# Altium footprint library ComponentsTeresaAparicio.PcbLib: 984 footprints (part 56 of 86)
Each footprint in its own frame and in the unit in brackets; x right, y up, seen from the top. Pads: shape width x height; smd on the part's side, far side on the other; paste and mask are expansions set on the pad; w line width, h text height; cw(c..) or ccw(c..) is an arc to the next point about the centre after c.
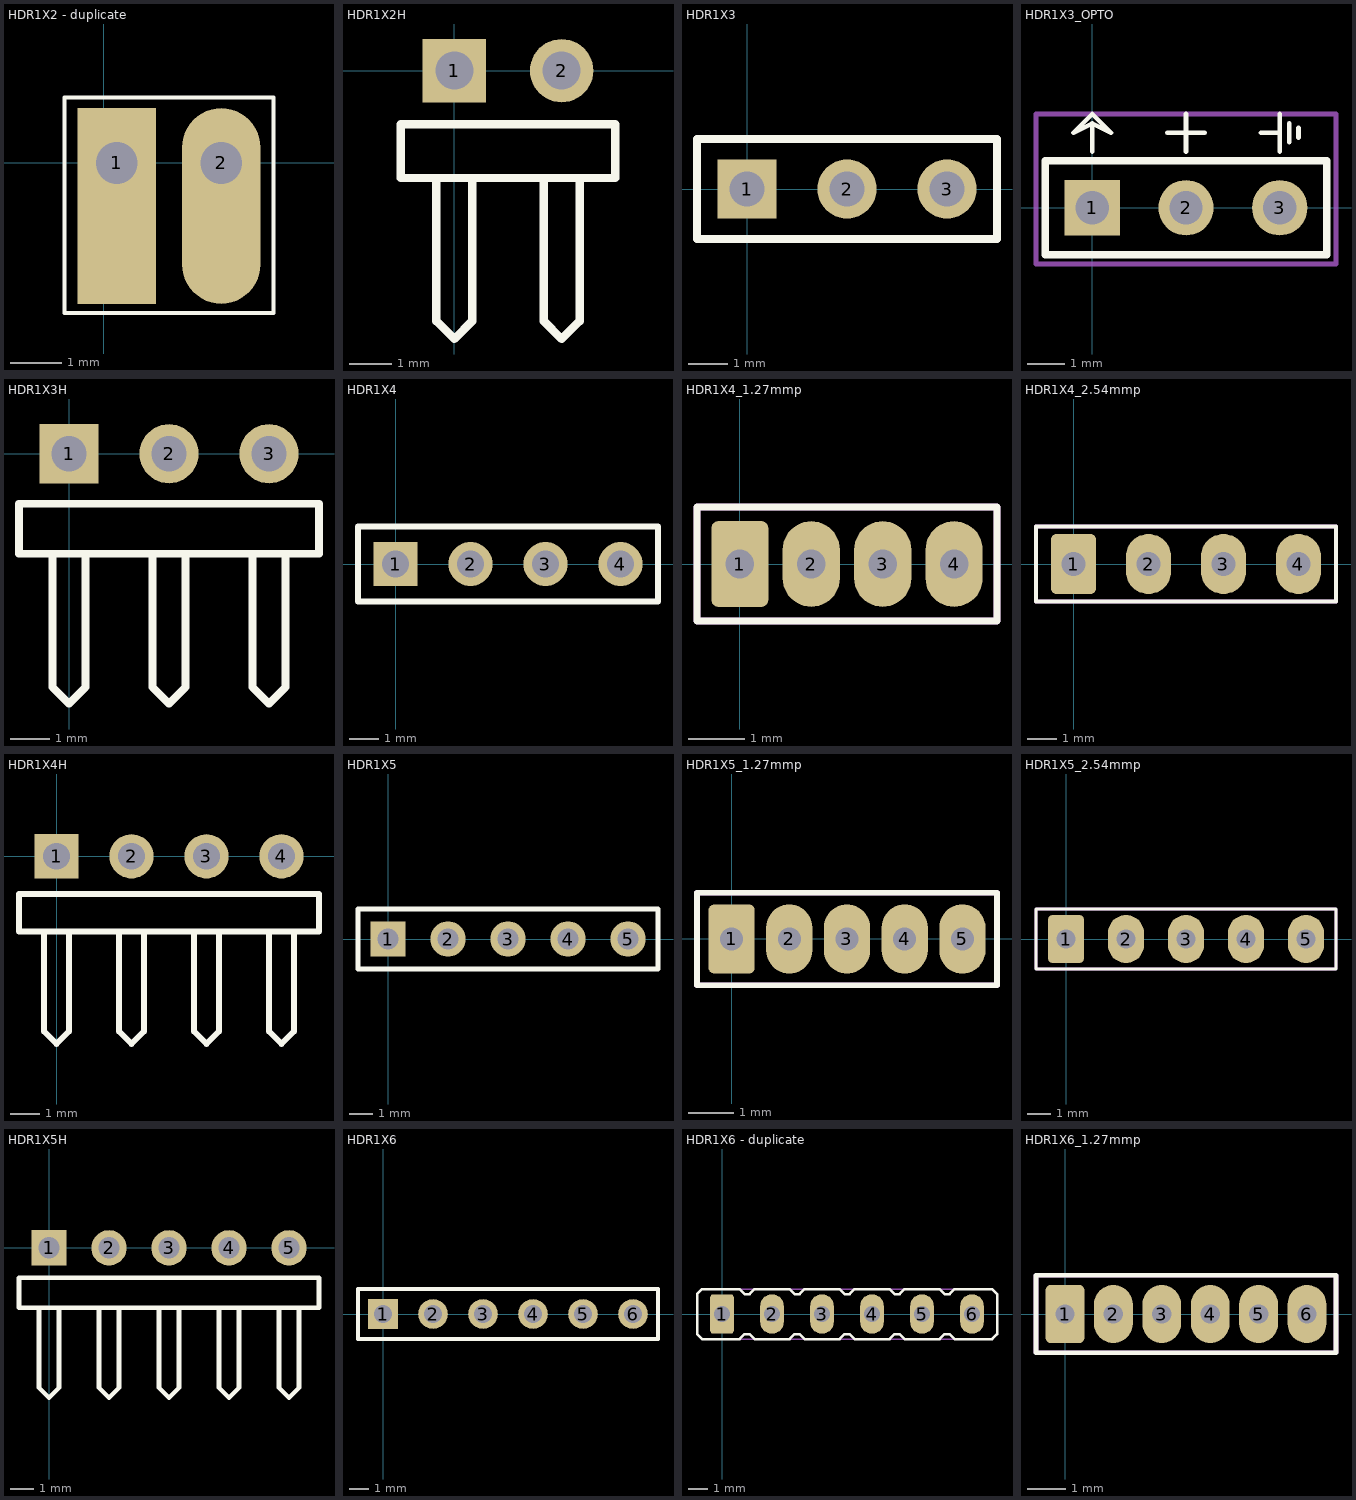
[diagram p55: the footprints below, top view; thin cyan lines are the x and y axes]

## HDR1X2 - duplicate [mil] "Connector; Header; 2 Position"
pads (2):
  rect 60x150 hole 32 copper offset 0,-33: 1(10,0)
  oval 60x150 hole 32 copper offset 0,-33: 2(90,0)
Top Overlay:
  lines w3: -30,-115 -30,50 130,50 130,-115 -30,-115

## HDR1X2H [mm] "Connector; Header; 2 Position; Right Angle"
pads (2):
  rect 1.5x1.5 hole 0.9: 1(0,0)
  round 1.5 hole 0.9: 2(2.54,0)
Top Overlay:
  lines w0.2: -0.423,-2.54 -0.423,-5.927 0,-6.35 0.423,-5.927 0.423,-2.54 ; 2.117,-2.54 2.117,-5.927 2.54,-6.35 2.963,-5.927 2.963,-2.54 ; -1.27,-2.54 3.81,-2.54 3.81,-1.27 -1.27,-1.27 -1.27,-2.54

## HDR1X3 [mm] "Connector; Header; 3 Position"
pads (3):
  rect 1.5x1.5 hole 0.9: 1(0,0)
  round 1.5 hole 0.9: 2(2.54,0) 3(5.08,0)
Top Overlay:
  lines w0.2: -1.27,-1.27 -1.27,1.27 6.35,1.27 6.35,-1.27 -1.27,-1.27

## HDR1X3_OPTO [mm] "Connector; Header; 3 Position"
pads (3):
  rect 1.5x1.5 hole 0.9: 1(0,0)
  round 1.5 hole 0.9: 2(2.54,0) 3(5.08,0)
Top Overlay:
  lines w0.127: 0,1.524 0,2.286 ; 2.032,2.032 3.048,2.032 ; 2.54,1.524 2.54,2.54 ; 4.572,2.032 5.08,2.032 5.08,2.54 5.08,1.524 ; 5.334,1.778 5.334,2.286 ; 5.588,1.905 5.588,2.159 ; 0,2.286 0.508,2.032 0,2.54 -0.508,2.032 0,2.286
  lines w0.2: -1.27,-1.27 6.35,-1.27 6.35,1.27 -1.27,1.27 -1.27,-1.27
Mechanical 14:
  lines w0.127: -1.524,-1.524 6.604,-1.524 6.604,2.54 -1.524,2.54 -1.524,-1.524

## HDR1X3H [mm] "Connector; Header; 3 Position; Right Angle"
pads (3):
  rect 1.5x1.5 hole 0.9: 1(0,0)
  round 1.5 hole 0.9: 2(2.54,0) 3(5.08,0)
Top Overlay:
  lines w0.2: -0.423,-2.54 -0.423,-5.927 0,-6.35 0.423,-5.927 0.423,-2.54 ; 2.117,-2.54 2.117,-5.927 2.54,-6.35 2.963,-5.927 2.963,-2.54 ; 4.657,-2.54 4.657,-5.927 5.08,-6.35 5.503,-5.927 5.503,-2.54 ; -1.27,-2.54 -1.27,-1.27 6.35,-1.27 6.35,-2.54 -1.27,-2.54

## HDR1X4 [mm] "Connector; Header; 4 Position"
pads (4):
  rect 1.5x1.5 hole 0.9: 1(0,0)
  round 1.5 hole 0.9: 2(2.54,0) 3(5.08,0) 4(7.62,0)
Top Overlay:
  lines w0.2: -1.27,-1.27 8.89,-1.27 8.89,1.27 -1.27,1.27 -1.27,-1.27

## HDR1X4_1.27mmp [mil] "Connector; Header; 4 Position, 0.050\" pitch"
pads (4):
  rrect25% 40x60 hole 20: 1(0,0)
  oval 40x60 hole 20: 2(50,0) 3(100,0) 4(150,0)
Top Overlay:
  lines w5: -30,-40 180,-40 180,40 -30,40 -30,-40
Mechanical 13:
  lines w5: -30,-40 180,-40 180,40 -30,40 -30,-40

## HDR1X4_2.54mmp [mil] "Connector; Header; 4 Position 0.100\" pitch"
pads (4):
  rrect25% 60x80 hole 32: 1(0,0)
  oval 60x80 hole 32: 2(100,0) 3(200,0) 4(300,0)
Top Overlay:
  lines w5: -50,-50 -50,50 350,50 350,-50 -50,-50
Mechanical 13:
  lines w5: -50,-50 350,-50 350,50 -50,50 -50,-50

## HDR1X4H [mm] "Connector; Header; 4 Position; Right Angle"
pads (4):
  rect 1.5x1.5 hole 0.9: 1(0,0)
  round 1.5 hole 0.9: 2(2.54,0) 3(5.08,0) 4(7.62,0)
Top Overlay:
  lines w0.2: -0.423,-2.54 -0.423,-5.927 0,-6.35 0.423,-5.927 0.423,-2.54 ; 2.117,-2.54 2.117,-5.927 2.54,-6.35 2.963,-5.927 2.963,-2.54 ; 4.657,-2.54 4.657,-5.927 5.08,-6.35 5.503,-5.927 5.503,-2.54 ; 7.197,-2.54 7.197,-5.927 7.62,-6.35 8.043,-5.927 8.043,-2.54 ; -1.27,-2.54 8.89,-2.54 8.89,-1.27 -1.27,-1.27 -1.27,-2.54

## HDR1X5 [mm] "Connector; Header; 5 Position"
pads (5):
  rect 1.5x1.5 hole 0.9: 1(0,0)
  round 1.5 hole 0.9: 2(2.54,0) 3(5.08,0) 4(7.62,0) 5(10.16,0)
Top Overlay:
  lines w0.2: -1.27,-1.27 11.43,-1.27 11.43,1.27 -1.27,1.27 -1.27,-1.27

## HDR1X5_1.27mmp [mil] "Connector; Header; 5 Position, 0.050\" pitch"
pads (5):
  rrect25% 40x60 hole 20: 1(0,0)
  oval 40x60 hole 20: 2(50,0) 3(100,0) 4(150,0) 5(200,0)
Top Overlay:
  lines w5: -30,-40 230,-40 230,40 -30,40 -30,-40
Mechanical 13:
  lines w5: -30,-40 230,-40 230,40 -30,40 -30,-40

## HDR1X5_2.54mmp [mil] "Connector; Header; 5 Position 0.100\" pitch"
pads (5):
  rrect25% 60x80 hole 32: 1(0,0)
  oval 60x80 hole 32: 2(100,0) 3(200,0) 4(300,0) 5(400,0)
Top Overlay:
  lines w5: -50,-50 -50,50 450,50 450,-50 -50,-50
Mechanical 13:
  lines w5: -50,-50 450,-50 450,50 -50,50 -50,-50

## HDR1X5H [mm] "Connector; Header; 5 Position; Right Angle"
pads (5):
  rect 1.5x1.5 hole 0.9: 1(0,0)
  round 1.5 hole 0.9: 2(2.54,0) 3(5.08,0) 4(7.62,0) 5(10.16,0)
Top Overlay:
  lines w0.2: -0.423,-2.54 -0.423,-5.927 0,-6.35 0.423,-5.927 0.423,-2.54 ; 2.117,-2.54 2.117,-5.927 2.54,-6.35 2.963,-5.927 2.963,-2.54 ; 4.657,-2.54 4.657,-5.927 5.08,-6.35 5.503,-5.927 5.503,-2.54 ; 7.197,-2.54 7.197,-5.927 7.62,-6.35 8.043,-5.927 8.043,-2.54 ; 9.737,-2.54 9.737,-5.927 10.16,-6.35 10.583,-5.927 10.583,-2.54 ; -1.27,-2.54 11.43,-2.54 11.43,-1.27 -1.27,-1.27 -1.27,-2.54

## HDR1X6 [mm] "Connector; Header; 6 Position"
pads (6):
  rect 1.5x1.5 hole 0.9: 1(0,0)
  round 1.5 hole 0.9: 2(2.54,0) 3(5.08,0) 4(7.62,0) 5(10.16,0) 6(12.7,0)
Top Overlay:
  lines w0.2: -1.27,-1.27 -1.27,1.27 13.97,1.27 13.97,-1.27 -1.27,-1.27

## HDR1X6 - duplicate [mm] "Connector; Header; 6 Position"
pads (6):
  rrect25% 1.2x2 hole 0.813: 1(0,0)
  oval 1.2x2 hole 0.813: 2(2.54,0) 3(5.08,0) 4(7.62,0) 5(10.16,0) 6(12.7,0)
Top Overlay:
  lines w0.127: -1.27,-1.016 -1.016,-1.27 0.889,-1.27 1.143,-1.016 1.397,-1.016 1.651,-1.27 3.429,-1.27 3.683,-1.016 3.937,-1.016 4.191,-1.27 5.969,-1.27 6.223,-1.016 6.477,-1.016 6.731,-1.27 8.509,-1.27 8.763,-1.016 9.017,-1.016 9.271,-1.27 11.049,-1.27 11.303,-1.016 11.557,-1.016 11.811,-1.27 13.716,-1.27 13.97,-1.016 13.97,1.016 13.716,1.27 11.811,1.27 11.557,1.016 11.303,1.016 11.049,1.27 9.271,1.27 9.017,1.016 8.763,1.016 8.509,1.27 6.731,1.27 6.477,1.016 6.223,1.016 5.969,1.27 4.191,1.27 3.937,1.016 3.683,1.016 3.429,1.27 1.651,1.27 1.397,1.016 1.143,1.016 0.889,1.27 -1.016,1.27 -1.27,1.016 -1.27,-1.016
Mechanical 13:
  lines w0.076: -1.27,-1.016 -1.27,1.016 -1.016,1.27 13.716,1.27 13.97,1.016 13.97,-1.016 13.716,-1.27 -1.016,-1.27 -1.27,-1.016

## HDR1X6_1.27mmp [mil] "Connector; Header; 6 Position, 0.050\" pitch"
pads (6):
  rrect25% 40x60 hole 20: 1(0,0)
  oval 40x60 hole 20: 2(50,0) 3(100,0) 4(150,0) 5(200,0) 6(250,0)
Top Overlay:
  lines w5: -30,-40 280,-40 280,40 -30,40 -30,-40
Bottom Solder:
  rectangle: 0,-30 250,30
Mechanical 13:
  lines w5: -30,-40 280,-40 280,40 -30,40 -30,-40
